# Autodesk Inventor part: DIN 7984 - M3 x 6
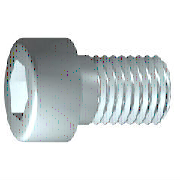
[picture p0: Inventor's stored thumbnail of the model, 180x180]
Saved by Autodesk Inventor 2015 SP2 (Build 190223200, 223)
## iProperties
IsCustomPart: 0
Created: 2012-02
Part Number: DIN 7984 - M3 x 6
Material: Stahl, weich
Description: Zylinderkopfschraube
Document SubType Name: Modeling
Standard: DIN 7984
Designer: rYan
Standard Revision: 1985
Standards Organization: DIN
Language: de-DE
Size Designation: M3 x 6
Categories: <MemberInstance><Categories><Category DisplayName="Verbindungselemente" InternalName="e4da775c-781d-43d5-af7c-5136215cf5a6" Mnemonic="FSTN"><Category DisplayNam
Density: 7.85 g/cm^3
Mass: 0.652401 g
Surface Area: 1.45477 cm^2
Volume: 0.0831084 cm^3
Appearance: Halbpoliert
Author: rYan
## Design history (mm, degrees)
sketch "Skizze1"
  geometry: L1 (0.167, 0)-(6, 0); L2 (6, 0)-(6, 1.5); L3 (6, 1.5)-(1.5, 1.5); L4 (1.5, 1.5)-(1.193, 1.5); L5 (1.193, 1.5)-(0, 1.5); L6 (0, 1.5)-(0, 2.75); L7 (0, 2.75)-(-2, 2.75); L8 (-2, 2.75)-(-2, 1.155); L9 (-2, 1.155)-(-0.5, 1.155); L10 (-0.5, 1.155)-(0.167, 0); L11 (-3.6, 0)-(7.6, 0) reference; L12 (0, -0.55)-(0, 3.3) reference; L13 (1.5, 1.5)-(0, 1.5)
  constraints: 22 end point, 6 parallel, 2 collinear, 2 perpendicular, 1 horizontal, 1 point on line
  dimensions: "d1" = 4.5 distance from line of L3.end L2 (= GEL); "d2" = 0.30683 distance of L4.end L3.end (computed from GAL); "d3" = 2 distance between parallel lines of L8 L6 (= KOH); "d4" = 1.5 distance of L8.end L9.end (= INTI); "d5" = 60 deg angle of L10 L1; "d6" = 3 diameter of L3 L1 (= GD); "d7" = 3 diameter of L5 L1 (= BDM); "d8" = 2.3094 diameter of L9 L1 (= 1.1547 x SW); "d9" = 5.5 diameter of L7 L1 (= KOD); "d26" = 6 distance between parallel lines of L12 L2 (= NLG)
revolve "Körper" sketch "Skizze1" stored, may be unused: angle "d10" = 90 deg
sketch "Skizze2"
  geometry: L1 (0, -3.85)-(0, 3.85) reference; L2 (-3.85, 0)-(3.85, 0) reference; L3 (1.155, 0)-(0.577, -1); L4 (0.577, -1)-(-0.577, -1); L5 (-0.577, -1)-(-1.155, 0); L6 (-1.155, 0)-(-0.577, 1); L7 (-0.577, 1)-(0.577, 1); L8 (0.577, 1)-(1.155, 0); 2 further points
  constraints: 12 end point, 1 coincident, 1 horizontal alignment, 1 point on line, 12 other
extrude "Loch" join sketch "Skizze2" stored distance "d11" = 10; taper "d12" = 0 deg
workplane "Work Plane1"
fillet "Fillet2" dims "d30" = 0.1 (= R)
body "Solid1"
fillet "Rundung1" dims "d17" = 0.3 (= RR)
feature "Gewinde" dims "d13" = 4.5 (= GEL), "d14" = 0
chamfer "Fase1" distance "d15" = 0.30673 (= -0.5 x SPD + 0.5 x GD); stored, may be unused: second distance "d16" = 0.30673 (= GUL), angle "d27" = 45 deg
other parameters: "GD" = 3 (= NND) [user parameter; used in 2 equation terms], "NLG" = 6 [user parameter; used in 1 equation term], "GEL" = 4.5 [user parameter; used in 2 equation terms], "KOD" = 5.5 [user parameter; used in 1 equation term], "KOH" = 2 [user parameter; used in 1 equation term], "INTI" = 1.5 [user parameter; used in 1 equation term], "GAL" = 0.30673 (= 0.61345 x PTC) [user parameter; used in 1 equation term], "GUL" = 0.30673 (= 0.61345 x PTC) [user parameter; used in 1 equation term], "BDM" = 3 (= NND) [user parameter; used in 1 equation term], "SW" = 2 [user parameter; used in 2 equation terms], "RR" = 0.3 [user parameter; used in 1 equation term], "SPD" = 2.38655 (= NND - 1.2269 x PTC) [user parameter; used in 1 equation term], "d19" = 0, "d28" = 0, "d29" = 0, "R" = 0.1 [user parameter; used in 1 equation term], "TOA" = 30 deg [user parameter], "GD1" = 2.38655 (= THREADDIA - 1.2269 x PTC) [user parameter], "THREADDIA" = 3 [user parameter; used in 1 equation term], "FAWI" = 45 deg [user parameter], "ANG" = 120 deg [user parameter], "PTC" = 0.5 [user parameter; used in 5 equation terms], "NND" = 3 [user parameter; used in 3 equation terms], "E0" = 2.31 (= 1.155 x SW) [user parameter]
